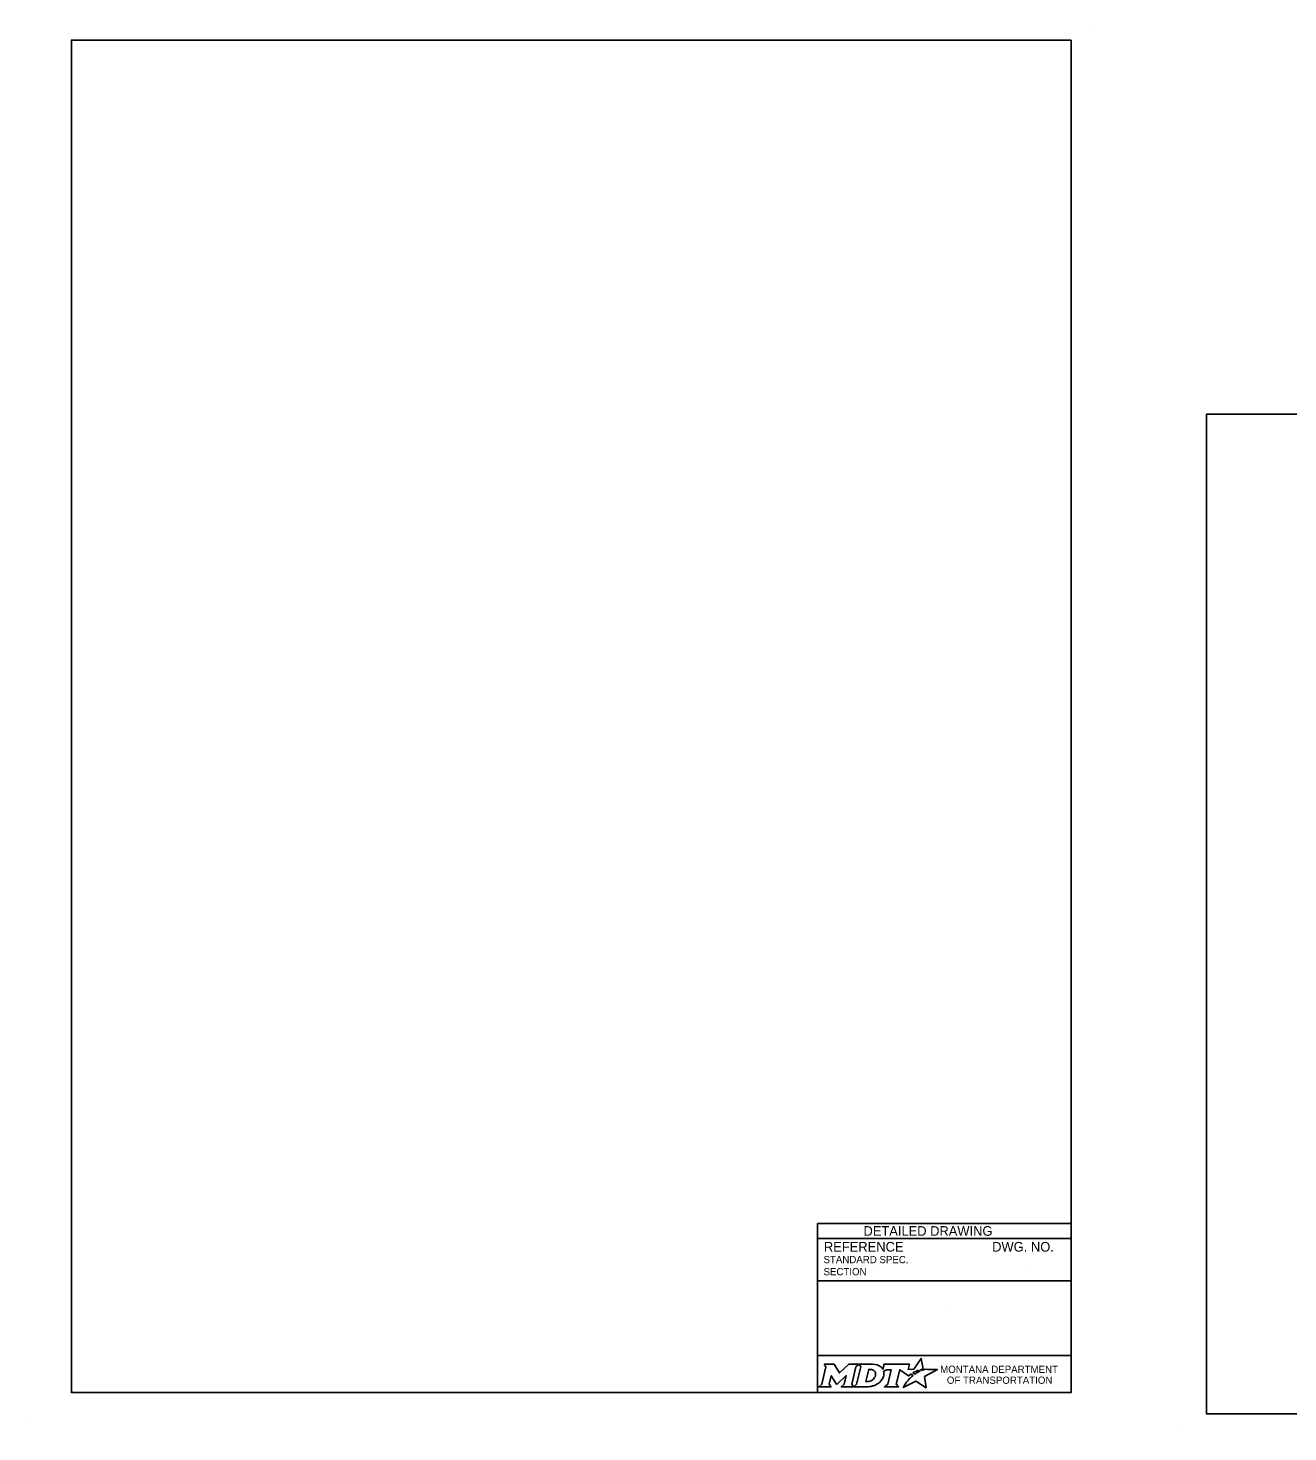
# Model space of a CAD drawing. Extents: x 49991 to 81321, y 49988 to 50028.
# Drawn here: x 49999.98 to 50010.41, y 49999.74 to 50011.36 of the extents above; entities that cross this region are included whole.
import ezdxf

# ---------------------------------------------------------------- set-up
doc = ezdxf.new("R2010")
doc.units = 0
doc.layers.add('Level 1', color=7, linetype='Continuous')
doc.layers.add('Level 2', color=7, linetype='Continuous')

msp = doc.modelspace()

# ---------------------------------------------------------------- linework, layer by layer
at = {"layer": 'Level 1'}
for p, q in [((50008.765, 50011.363), (50008.765, 50011.363)), ((49999.977, 49999.862), (49999.977, 49999.862)), ((50009.537, 49999.736), (50009.537, 49999.736))]:
    msp.add_line(p, q, dxfattribs=at)
for points in [[(50008.615, 50011.263), (50000.336, 50011.263), (50000.336, 50000.062), (50008.615, 50000.062)], [(50020.938, 50008.165), (50009.737, 50008.165), (50009.737, 49999.886), (50020.938, 49999.886)]]:
    msp.add_lwpolyline(points, close=True, dxfattribs=at)
at = {"layer": 'Level 2'}
for p, q in [((50008.615, 50001.462), (50006.515, 50001.462)), ((50006.515, 50001.462), (50006.515, 50000.062)), ((50008.615, 50001.337), (50006.515, 50001.337)), ((50007.009, 50001.063), (50007.009, 50001.063)), ((50008.251, 50001.122), (50008.251, 50001.122)), ((50008.615, 50000.987), (50006.515, 50000.987)), ((50007.565, 50000.738), (50007.565, 50000.738)), ((50008.615, 50000.369), (50006.515, 50000.369))]:
    msp.add_line(p, q, dxfattribs=at)
for points in [[(50007.377, 50000.245), (50007.367, 50000.25), (50007.378, 50000.253), (50007.39, 50000.255), (50007.373, 50000.345), (50007.313, 50000.254), (50007.266, 50000.253), (50007.276, 50000.297), (50007.067, 50000.297), (50007.057, 50000.255), (50007.051, 50000.263)], [(50006.57, 50000.297), (50006.584, 50000.274), (50006.551, 50000.131), (50006.525, 50000.108), (50006.627, 50000.108), (50006.613, 50000.131), (50006.629, 50000.201), (50006.673, 50000.132), (50006.678, 50000.132), (50006.753, 50000.202), (50006.737, 50000.13), (50006.712, 50000.108), (50006.814, 50000.108), (50006.8, 50000.132), (50006.833, 50000.274)], [(50006.833, 50000.274), (50006.859, 50000.297), (50006.776, 50000.297), (50006.697, 50000.224), (50006.652, 50000.297), (50006.57, 50000.297)], [(50006.972, 50000.297), (50006.859, 50000.297), (50006.873, 50000.275), (50006.839, 50000.131), (50006.814, 50000.108), (50006.925, 50000.108)], [(50006.996, 50000.211), (50006.995, 50000.203), (50006.992, 50000.193), (50006.988, 50000.185), (50006.982, 50000.178), (50006.976, 50000.171), (50006.968, 50000.164), (50006.959, 50000.16), (50006.95, 50000.156), (50006.941, 50000.154), (50006.932, 50000.153), (50006.916, 50000.153), (50006.94, 50000.253), (50006.956, 50000.253), (50006.963, 50000.252), (50006.971, 50000.25), (50006.977, 50000.247), (50006.983, 50000.243), (50006.988, 50000.238), (50006.992, 50000.232), (50006.995, 50000.226), (50006.996, 50000.218), (50006.996, 50000.215), (50006.996, 50000.211)], [(50007.064, 50000.238), (50007.088, 50000.251), (50007.125, 50000.251), (50007.097, 50000.131), (50007.069, 50000.108), (50007.185, 50000.108), (50007.168, 50000.131), (50007.196, 50000.251), (50007.268, 50000.2), (50007.289, 50000.215), (50007.309, 50000.204)], [(50007.253, 50000.148), (50007.237, 50000.124), (50007.233, 50000.116), (50007.227, 50000.107), (50007.225, 50000.103), (50007.33, 50000.156), (50007.414, 50000.101), (50007.401, 50000.194), (50007.508, 50000.252), (50007.458, 50000.253), (50007.428, 50000.253), (50007.407, 50000.254), (50007.401, 50000.252), (50007.396, 50000.251), (50007.387, 50000.249), (50007.377, 50000.245)], [(50007.327, 50000.217), (50007.324, 50000.215), (50007.306, 50000.225), (50007.316, 50000.231), (50007.32, 50000.233), (50007.329, 50000.237), (50007.335, 50000.239), (50007.343, 50000.243), (50007.35, 50000.245), (50007.362, 50000.238), (50007.358, 50000.236), (50007.353, 50000.233), (50007.349, 50000.231), (50007.344, 50000.228), (50007.342, 50000.227), (50007.339, 50000.225), (50007.337, 50000.224), (50007.334, 50000.222), (50007.332, 50000.221), (50007.329, 50000.219), (50007.327, 50000.217)], [(50006.97, 50000.116), (50006.979, 50000.118), (50006.992, 50000.124), (50007.012, 50000.135)], [(50007.267, 50000.164), (50007.267, 50000.164)]]:
    msp.add_lwpolyline(points, dxfattribs=at)
for centre, radius, start, end in [((50006.995, 50000.219), 0.0709, 339.5329, 15.8582), ((50006.951, 50000.236), 0.118, 300.9103, 339.1383)]:
    msp.add_arc(centre, radius, start, end, dxfattribs=at)
for centre, major_axis, ratio, start_param, end_param in [((50006.97, 50000.25), (0.0834, -0.0037), 0.568097, 0.61298, 1.570796), ((50007.026, 50000.257), (0.0361, -0.0295), 0.469099, 1.225588, 1.570796), ((50006.925, 50000.257), (0, 0.148), 0.987302, 3.139398, 3.456847), ((50007.26, 50000.156), (-0.00694, -0.00806), 0.008222, 0, 3.137361), ((50007.276, 50000.174), (-0.0098, -0.0102), 0.016458, 3.141593, 6.279097), ((50007.297, 50000.194), (-0.0112, -0.0097), 0.021651, 3.157348, 6.283185)]:
    msp.add_ellipse(centre, major_axis=major_axis, ratio=ratio, start_param=start_param, end_param=end_param, dxfattribs=at)

# ---------------------------------------------------------------- texts
for s, height, p in [('DETAILED DRAWING', 0.0799, (50006.896, 50001.36)), ('REFERENCE', 0.08, (50006.568, 50001.229)), ('DWG. NO.', 0.08, (50007.962, 50001.229)), ('STANDARD SPEC.', 0.06, (50006.565, 50001.133)), ('SECTION', 0.06, (50006.565, 50001.033)), ('MONTANA DEPARTMENT', 0.06, (50007.531, 50000.224)), ('OF TRANSPORTATION', 0.06, (50007.587, 50000.134))]:
    msp.add_text(s, height=height, dxfattribs=at).set_placement(p)

doc.saveas('drawing.dxf')
